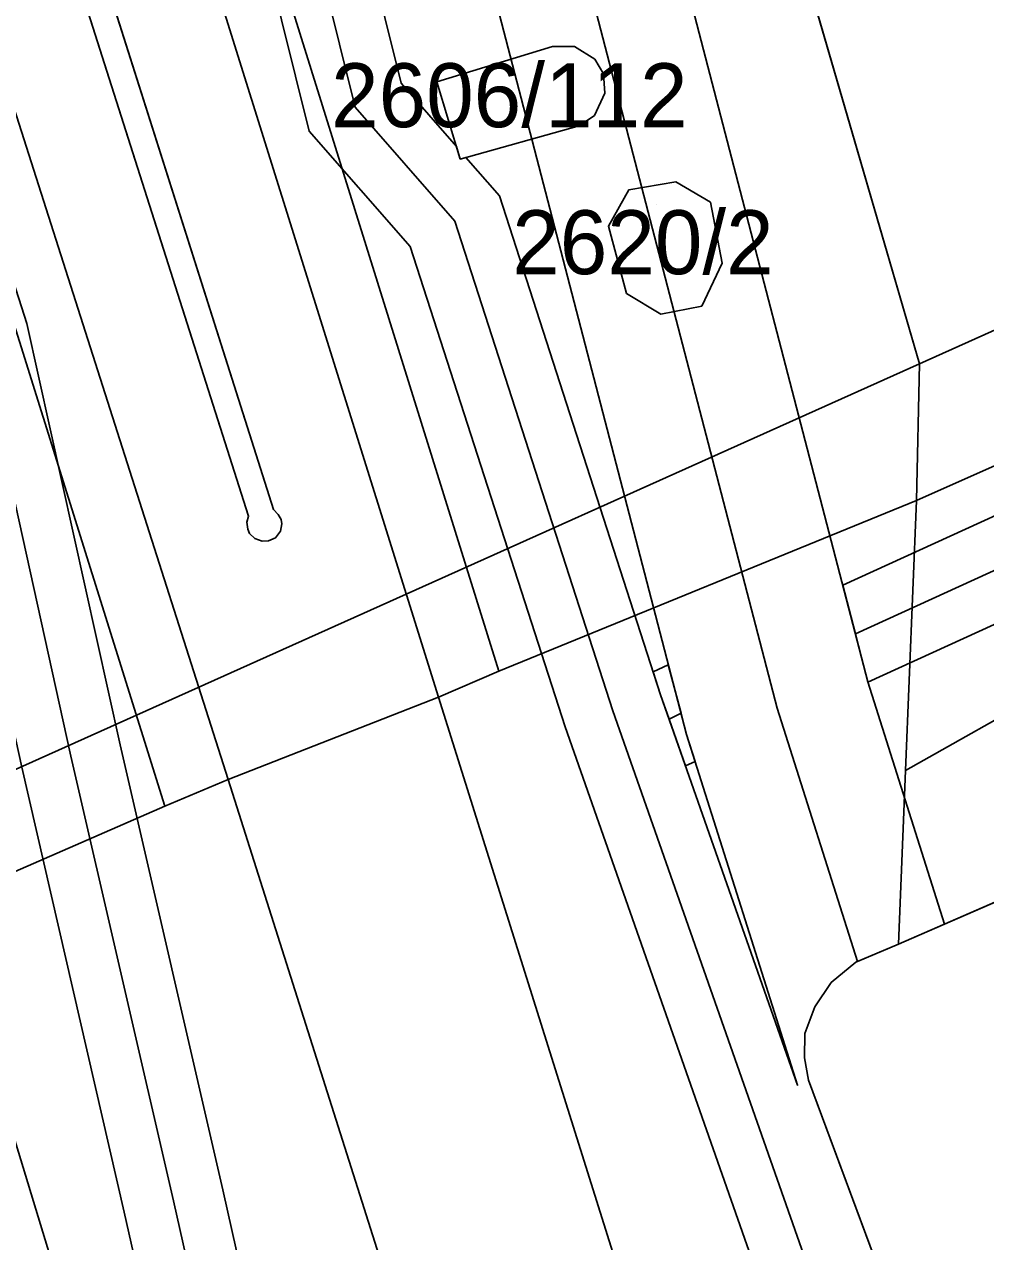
# Model space of a CAD drawing. Extents: x -263423 to -261326, y -1240067 to -1237864.
# Drawn here: x -262699.95 to -262669.87, y -1239884.91 to -1239846.82 of the extents above; entities that cross this region are included whole.
import ezdxf

# ---------------------------------------------------------------- set-up
doc = ezdxf.new("R2010")
doc.units = 0
for name, color, linetype in [('body_kn', 7, 'Continuous'), ('kladpar_druhypozemkov', 7, 'Continuous'), ('kladpar_hranice', 7, 'Continuous'), ('kladpar_parcelnecisla', 7, 'Continuous'), ('kladpar_plochy', 7, 'Continuous'), ('linie', 7, 'Continuous'), ('tarchy_linie', 7, 'Continuous'), ('zappar_hrandruhpozemk', 7, 'Continuous')]:
    doc.layers.add(name, color=color, linetype=linetype)

msp = doc.modelspace()

# ---------------------------------------------------------------- linework, layer by layer
at = {"layer": 'body_kn'}
for p, q in [((-262683.42, -1239847.51), (-262683.42, -1239847.51)), ((-262682.73, -1239847.51), (-262682.73, -1239847.51)), ((-262682.1, -1239847.91), (-262682.1, -1239847.91)), ((-262681.83, -1239848.37), (-262681.83, -1239848.37)), ((-262688.16, -1239848.66), (-262688.16, -1239848.66)), ((-262687.04, -1239848.62), (-262687.04, -1239848.62)), ((-262687.04, -1239848.62), (-262687.04, -1239848.62)), ((-262681.78, -1239848.97), (-262681.78, -1239848.97)), ((-262689.6, -1239849.41), (-262689.6, -1239849.41)), ((-262682.11, -1239849.67), (-262682.11, -1239849.67)), ((-262691.04, -1239850.16), (-262691.04, -1239850.16)), ((-262682.59, -1239850), (-262682.59, -1239850)), ((-262686.43, -1239850.64), (-262686.43, -1239850.64)), ((-262686.31, -1239851.04), (-262686.31, -1239851.04)), ((-262686.13, -1239850.99), (-262686.13, -1239850.99)), ((-262679.56, -1239851.75), (-262679.56, -1239851.75)), ((-262685.08, -1239852.19), (-262685.08, -1239852.19)), ((-262681.03, -1239852), (-262681.03, -1239852)), ((-262678.48, -1239852.39), (-262678.48, -1239852.39)), ((-262678.48, -1239852.39), (-262678.48, -1239852.39)), ((-262686.48, -1239852.98), (-262686.48, -1239852.98)), ((-262681.67, -1239853.14), (-262681.67, -1239853.14)), ((-262687.88, -1239853.77), (-262687.88, -1239853.77)), ((-262678.11, -1239854.3), (-262678.11, -1239854.3)), ((-262681.11, -1239855.24), (-262681.11, -1239855.24)), ((-262678.75, -1239855.64), (-262678.75, -1239855.64)), ((-262680.03, -1239855.89), (-262680.03, -1239855.89)), ((-262699.87, -1239856.18), (-262699.87, -1239856.18)), ((-262671.94, -1239857.45), (-262671.94, -1239857.45)), ((-262672.03, -1239861.72), (-262672.03, -1239861.72)), ((-262672.03, -1239861.72), (-262672.03, -1239861.72)), ((-262692.15, -1239862), (-262692.15, -1239862)), ((-262692.01, -1239862.16), (-262692.01, -1239862.16)), ((-262692.99, -1239862.4), (-262692.99, -1239862.4)), ((-262692.99, -1239862.4), (-262692.99, -1239862.4)), ((-262692.93, -1239862.21), (-262692.93, -1239862.21)), ((-262691.91, -1239862.32), (-262691.91, -1239862.32)), ((-262691.89, -1239862.45), (-262691.89, -1239862.45)), ((-262692.96, -1239862.62), (-262692.96, -1239862.62)), ((-262692.9, -1239862.75), (-262692.9, -1239862.75)), ((-262692.74, -1239862.91), (-262692.74, -1239862.91)), ((-262692.09, -1239862.89), (-262692.09, -1239862.89)), ((-262691.93, -1239862.68), (-262691.93, -1239862.68)), ((-262692.51, -1239862.99), (-262692.51, -1239862.99)), ((-262692.31, -1239862.98), (-262692.31, -1239862.98)), ((-262674.34, -1239864.37), (-262674.34, -1239864.37)), ((-262673.94, -1239865.89), (-262673.94, -1239865.89)), ((-262673.94, -1239865.89), (-262673.94, -1239865.89)), ((-262685.1, -1239867.06), (-262685.1, -1239867.06)), ((-262680.27, -1239867.08), (-262680.27, -1239867.08)), ((-262680.27, -1239867.08), (-262680.27, -1239867.08)), ((-262679.8, -1239866.86), (-262679.8, -1239866.86)), ((-262673.55, -1239867.4), (-262673.55, -1239867.4)), ((-262673.55, -1239867.41), (-262673.55, -1239867.41)), ((-262680.04, -1239867.8), (-262680.04, -1239867.8)), ((-262686.99, -1239867.88), (-262686.99, -1239867.88)), ((-262686.99, -1239867.88), (-262686.99, -1239867.88)), ((-262676.39, -1239868.22), (-262676.39, -1239868.22)), ((-262681.53, -1239868.3), (-262681.53, -1239868.3)), ((-262679.77, -1239868.56), (-262679.77, -1239868.56)), ((-262679.77, -1239868.56), (-262679.77, -1239868.56)), ((-262679.4, -1239868.38), (-262679.4, -1239868.38)), ((-262683.02, -1239868.8), (-262683.02, -1239868.8)), ((-262696.95, -1239869.37), (-262696.95, -1239869.37)), ((-262679.23, -1239869.04), (-262679.23, -1239869.04)), ((-262698.49, -1239869.72), (-262698.49, -1239869.72)), ((-262679.26, -1239870.02), (-262679.26, -1239870.02)), ((-262678.96, -1239869.89), (-262678.96, -1239869.89)), ((-262693.57, -1239870.45), (-262693.57, -1239870.45)), ((-262693.57, -1239870.45), (-262693.57, -1239870.45)), ((-262672.37, -1239870.17), (-262672.37, -1239870.17)), ((-262695.55, -1239871.29), (-262695.55, -1239871.29)), ((-262671.15, -1239874.98), (-262671.15, -1239874.98)), ((-262672.59, -1239875.61), (-262672.59, -1239875.61)), ((-262673.93, -1239876.17), (-262673.93, -1239876.17)), ((-262673.88, -1239876.15), (-262673.88, -1239876.15)), ((-262674.7, -1239876.81), (-262674.7, -1239876.81)), ((-262675.21, -1239877.57), (-262675.21, -1239877.57)), ((-262675.53, -1239878.4), (-262675.53, -1239878.4)), ((-262675.54, -1239879.16), (-262675.54, -1239879.16)), ((-262675.75, -1239880.02), (-262675.75, -1239880.02)), ((-262675.41, -1239879.86), (-262675.41, -1239879.86)), ((-262693.74, -1239883.29), (-262693.74, -1239883.29)), ((-262695.28, -1239883.64), (-262695.28, -1239883.64)), ((-262696.82, -1239883.99), (-262696.82, -1239883.99))]:
    msp.add_line(p, q, dxfattribs=at)
at = {"layer": 'kladpar_druhypozemkov'}
for p, q in [((-262684.11, -1239848.84), (-262684.11, -1239848.84)), ((-262680.16, -1239852.45), (-262680.16, -1239852.45))]:
    msp.add_line(p, q, dxfattribs=at)
at = {"layer": 'kladpar_hranice'}
for points in [[(-262692.99, -1239862.4), (-262692.93, -1239862.21), (-262714.7, -1239793.85)], [(-262714.7, -1239793.85), (-262692.93, -1239862.21)], [(-262713.85, -1239793.61), (-262692.15, -1239862), (-262692.01, -1239862.16), (-262691.91, -1239862.32), (-262691.89, -1239862.45), (-262691.93, -1239862.68), (-262692.09, -1239862.89), (-262692.31, -1239862.98), (-262692.51, -1239862.99), (-262692.74, -1239862.91), (-262692.9, -1239862.75), (-262692.96, -1239862.62), (-262692.99, -1239862.4)], [(-262692.93, -1239862.21), (-262692.99, -1239862.4), (-262692.96, -1239862.62), (-262692.9, -1239862.75), (-262692.74, -1239862.91), (-262692.51, -1239862.99), (-262692.31, -1239862.98), (-262692.09, -1239862.89), (-262691.93, -1239862.68), (-262691.89, -1239862.45), (-262691.91, -1239862.32), (-262692.01, -1239862.16), (-262692.15, -1239862), (-262713.85, -1239793.61)], [(-262686.78, -1239809.35), (-262684.33, -1239817.9), (-262683.63, -1239817.77), (-262683.37, -1239818.54), (-262682.24, -1239822.49), (-262682.63, -1239822.68), (-262680.93, -1239828.11), (-262680.48, -1239828.04), (-262679.23, -1239832.57), (-262679.61, -1239832.76), (-262677.91, -1239838.12), (-262677.6, -1239838.06), (-262676.46, -1239841.89), (-262671.94, -1239857.45), (-262672.03, -1239861.72), (-262672.37, -1239870.17), (-262672.59, -1239875.61), (-262673.93, -1239876.17), (-262674.7, -1239876.81), (-262675.21, -1239877.57), (-262675.53, -1239878.4), (-262675.54, -1239879.16), (-262675.41, -1239879.86), (-262662.51, -1239914.58)], [(-262663.27, -1239837.29), (-262662.12, -1239836.92), (-262662.31, -1239836.21), (-262659.95, -1239835.27), (-262658.67, -1239834.7), (-262657.92, -1239836.87), (-262659.19, -1239837.5), (-262657.24, -1239843.63), (-262654.63, -1239842.43), (-262652.39, -1239841.35), (-262648.06, -1239839.46), (-262648.88, -1239837.55), (-262647.79, -1239836.98), (-262650.38, -1239830.98), (-262640.17, -1239826.56), (-262633.99, -1239840.42), (-262649.81, -1239847.42), (-262651.98, -1239848.49), (-262671.94, -1239857.45), (-262676.46, -1239841.89), (-262663.27, -1239837.29)], [(-262687.04, -1239848.62), (-262683.42, -1239847.51), (-262682.73, -1239847.51), (-262682.1, -1239847.91), (-262681.83, -1239848.37), (-262681.78, -1239848.97), (-262682.11, -1239849.67), (-262682.59, -1239850), (-262686.31, -1239851.04), (-262687.04, -1239848.62)], [(-262683.42, -1239847.51), (-262687.04, -1239848.62), (-262686.31, -1239851.04), (-262682.59, -1239850), (-262682.11, -1239849.67), (-262681.78, -1239848.97), (-262681.83, -1239848.37), (-262682.1, -1239847.91), (-262682.73, -1239847.51), (-262683.42, -1239847.51)], [(-262666.09, -1239872.77), (-262672.59, -1239875.61), (-262672.37, -1239870.17), (-262672.03, -1239861.72), (-262671.94, -1239857.45), (-262651.98, -1239848.49)], [(-262678.48, -1239852.39), (-262678.11, -1239854.3), (-262678.75, -1239855.64), (-262680.03, -1239855.89), (-262681.11, -1239855.24), (-262681.67, -1239853.14), (-262681.03, -1239852), (-262679.56, -1239851.75), (-262678.48, -1239852.39)], [(-262678.11, -1239854.3), (-262678.48, -1239852.39), (-262679.56, -1239851.75), (-262681.03, -1239852), (-262681.67, -1239853.14), (-262681.11, -1239855.24), (-262680.03, -1239855.89), (-262678.75, -1239855.64), (-262678.11, -1239854.3)], [(-262662.51, -1239914.58), (-262675.41, -1239879.86), (-262675.54, -1239879.16), (-262675.53, -1239878.4), (-262675.21, -1239877.57), (-262674.7, -1239876.81), (-262673.93, -1239876.17), (-262672.59, -1239875.61), (-262666.09, -1239872.77)]]:
    msp.add_lwpolyline(points, dxfattribs=at)
at = {"layer": 'kladpar_plochy'}
for p, q in [((-262714.7, -1239793.85), (-262692.93, -1239862.21)), ((-262692.15, -1239862), (-262713.85, -1239793.61)), ((-262676.46, -1239841.89), (-262671.94, -1239857.45)), ((-262683.42, -1239847.51), (-262687.04, -1239848.62)), ((-262682.73, -1239847.51), (-262683.42, -1239847.51)), ((-262682.1, -1239847.91), (-262682.73, -1239847.51)), ((-262681.83, -1239848.37), (-262682.1, -1239847.91)), ((-262681.78, -1239848.97), (-262681.83, -1239848.37)), ((-262687.04, -1239848.62), (-262686.31, -1239851.04)), ((-262682.11, -1239849.67), (-262681.78, -1239848.97)), ((-262682.59, -1239850), (-262682.11, -1239849.67)), ((-262686.31, -1239851.04), (-262682.59, -1239850)), ((-262679.56, -1239851.75), (-262681.03, -1239852)), ((-262678.48, -1239852.39), (-262679.56, -1239851.75)), ((-262681.03, -1239852), (-262681.67, -1239853.14)), ((-262678.11, -1239854.3), (-262678.48, -1239852.39)), ((-262681.67, -1239853.14), (-262681.11, -1239855.24)), ((-262678.75, -1239855.64), (-262678.11, -1239854.3)), ((-262681.11, -1239855.24), (-262680.03, -1239855.89)), ((-262680.03, -1239855.89), (-262678.75, -1239855.64)), ((-262671.94, -1239857.45), (-262672.03, -1239861.72)), ((-262672.03, -1239861.72), (-262672.37, -1239870.17)), ((-262692.01, -1239862.16), (-262692.15, -1239862)), ((-262691.91, -1239862.32), (-262692.01, -1239862.16)), ((-262692.93, -1239862.21), (-262692.99, -1239862.4)), ((-262692.99, -1239862.4), (-262692.96, -1239862.62)), ((-262691.93, -1239862.68), (-262691.89, -1239862.45)), ((-262691.89, -1239862.45), (-262691.91, -1239862.32)), ((-262692.96, -1239862.62), (-262692.9, -1239862.75)), ((-262692.9, -1239862.75), (-262692.74, -1239862.91)), ((-262692.74, -1239862.91), (-262692.51, -1239862.99)), ((-262692.31, -1239862.98), (-262692.09, -1239862.89)), ((-262692.09, -1239862.89), (-262691.93, -1239862.68)), ((-262692.51, -1239862.99), (-262692.31, -1239862.98)), ((-262672.37, -1239870.17), (-262672.59, -1239875.61)), ((-262672.59, -1239875.61), (-262666.09, -1239872.77)), ((-262673.93, -1239876.17), (-262672.59, -1239875.61)), ((-262672.59, -1239875.61), (-262673.93, -1239876.17)), ((-262674.7, -1239876.81), (-262673.93, -1239876.17)), ((-262673.93, -1239876.17), (-262674.7, -1239876.81)), ((-262675.21, -1239877.57), (-262674.7, -1239876.81)), ((-262674.7, -1239876.81), (-262675.21, -1239877.57)), ((-262675.53, -1239878.4), (-262675.21, -1239877.57)), ((-262675.21, -1239877.57), (-262675.53, -1239878.4)), ((-262675.54, -1239879.16), (-262675.53, -1239878.4)), ((-262675.53, -1239878.4), (-262675.54, -1239879.16)), ((-262675.41, -1239879.86), (-262675.54, -1239879.16)), ((-262675.54, -1239879.16), (-262675.41, -1239879.86)), ((-262662.51, -1239914.58), (-262675.41, -1239879.86)), ((-262675.41, -1239879.86), (-262662.51, -1239914.58))]:
    msp.add_line(p, q, dxfattribs=at)
for points in [[(-262713.85, -1239793.61), (-262692.15, -1239862), (-262692.01, -1239862.16), (-262691.91, -1239862.32), (-262691.89, -1239862.45), (-262691.93, -1239862.68), (-262692.09, -1239862.89), (-262692.31, -1239862.98), (-262692.51, -1239862.99), (-262692.74, -1239862.91), (-262692.9, -1239862.75), (-262692.96, -1239862.62), (-262692.99, -1239862.4), (-262692.93, -1239862.21), (-262714.7, -1239793.85)], [(-262666.09, -1239872.77), (-262672.59, -1239875.61), (-262672.37, -1239870.17), (-262672.03, -1239861.72), (-262671.94, -1239857.45), (-262651.98, -1239848.49)]]:
    msp.add_lwpolyline(points, dxfattribs=at)
for points in [[(-262663.27, -1239837.29), (-262662.12, -1239836.92), (-262662.31, -1239836.21), (-262659.95, -1239835.27), (-262658.67, -1239834.7), (-262657.92, -1239836.87), (-262659.19, -1239837.5), (-262657.24, -1239843.63), (-262654.63, -1239842.43), (-262652.39, -1239841.35), (-262648.06, -1239839.46), (-262648.88, -1239837.55), (-262647.79, -1239836.98), (-262650.38, -1239830.98), (-262640.17, -1239826.56), (-262633.99, -1239840.42), (-262649.81, -1239847.42), (-262651.98, -1239848.49), (-262671.94, -1239857.45), (-262676.46, -1239841.89)], [(-262687.04, -1239848.62), (-262683.42, -1239847.51), (-262682.73, -1239847.51), (-262682.1, -1239847.91), (-262681.83, -1239848.37), (-262681.78, -1239848.97), (-262682.11, -1239849.67), (-262682.59, -1239850), (-262686.31, -1239851.04)], [(-262678.48, -1239852.39), (-262678.11, -1239854.3), (-262678.75, -1239855.64), (-262680.03, -1239855.89), (-262681.11, -1239855.24), (-262681.67, -1239853.14), (-262681.03, -1239852), (-262679.56, -1239851.75)]]:
    msp.add_lwpolyline(points, close=True, dxfattribs=at)
at = {"layer": 'linie'}
msp.add_lwpolyline([(-262521.46, -1239790.07), (-262540.33, -1239798.65), (-262560.41, -1239807.74), (-262562.89, -1239808.81), (-262563.41, -1239809.03), (-262572.52, -1239812.91), (-262575.06, -1239814.02), (-262575.26, -1239814.11), (-262577.3, -1239815.05), (-262595.03, -1239823), (-262607.52, -1239828.24), (-262633.99, -1239840.42), (-262649.81, -1239847.42), (-262651.98, -1239848.49), (-262671.94, -1239857.45), (-262714.44, -1239876.51), (-262740.08, -1239884.8)], dxfattribs=at)
at = {"layer": 'tarchy_linie'}
msp.add_line((-262679.77, -1239868.56), (-262679.4, -1239868.38), dxfattribs=at)
for points in [[(-262876.1, -1239267.26), (-262859.65, -1239272.11), (-262836.46, -1239332.83), (-262813.8, -1239395.79), (-262782.96, -1239480.21), (-262751.68, -1239564.86), (-262738.56, -1239596.25), (-262720.83, -1239681.08), (-262703.16, -1239765.24), (-262676.39, -1239868.22), (-262673.88, -1239876.15)], [(-262673.94, -1239865.89), (-262591.1, -1239828.06), (-262563.05, -1239815.33), (-262497.85, -1239786.86), (-262417.23, -1239749.97)], [(-262700.29, -1239764.57), (-262673.55, -1239867.4), (-262671.15, -1239874.98), (-262672.59, -1239875.61), (-262673.88, -1239876.15), (-262673.93, -1239876.17), (-262674.7, -1239876.81), (-262675.21, -1239877.57), (-262675.53, -1239878.4), (-262675.54, -1239879.16), (-262675.41, -1239879.86), (-262662.51, -1239914.58), (-262657.08, -1239929.21), (-262650.11, -1239948.02), (-262649.29, -1239949.42), (-262648.47, -1239950.57), (-262647.52, -1239951.53), (-262646.71, -1239952.19), (-262642.79, -1239964.57), (-262676.62, -1239978.96), (-262706.54, -1239880.67), (-262742.27, -1239779.37)], [(-262704.88, -1239770.36), (-262679.23, -1239869.04), (-262675.75, -1239880.02), (-262680.04, -1239867.8), (-262685.08, -1239852.19), (-262686.13, -1239850.99), (-262686.31, -1239851.04), (-262686.43, -1239850.64), (-262688.16, -1239848.66), (-262695.33, -1239819.8), (-262695.68, -1239819.16), (-262695.52, -1239819.07), (-262696.63, -1239814.58), (-262697.18, -1239812.62), (-262697.12, -1239812.6), (-262698.35, -1239807.65), (-262704.2, -1239785.83), (-262704.62, -1239773.91), (-262704.88, -1239770.36)], [(-262733.86, -1239786.06), (-262731.31, -1239790.5), (-262727.77, -1239796.86), (-262723.05, -1239806.16), (-262717.47, -1239818.88), (-262715.31, -1239824.82), (-262709.31, -1239838.88), (-262708.04, -1239840.99), (-262702.91, -1239857), (-262700.03, -1239870.07), (-262696.82, -1239883.99), (-262694.57, -1239893.97), (-262689.49, -1239914.36), (-262686.73, -1239925.28), (-262678.36, -1239950.89), (-262673.78, -1239965.52), (-262673.54, -1239968), (-262672.3, -1239970.93), (-262673.02, -1239971.24), (-262701.12, -1239878.89), (-262733.86, -1239786.06)], [(-262497.22, -1239788.28), (-262562.42, -1239816.75), (-262590.46, -1239829.47), (-262673.55, -1239867.41), (-262673.55, -1239867.4), (-262673.94, -1239865.89), (-262674.34, -1239864.37), (-262591.74, -1239826.65), (-262565.09, -1239814.55)], [(-262701.41, -1239808.43), (-262691.04, -1239850.16), (-262687.88, -1239853.77), (-262683.02, -1239868.8), (-262675.02, -1239891.62), (-262660.7, -1239928.6), (-262653.54, -1239953.87), (-262651.61, -1239958.73), (-262670.45, -1239967.28), (-262670.68, -1239964.9), (-262675.36, -1239949.93), (-262683.71, -1239924.4), (-262686.43, -1239913.6), (-262691.51, -1239893.25), (-262693.74, -1239883.29), (-262696.95, -1239869.37), (-262699.87, -1239856.18), (-262705.16, -1239839.69), (-262706.49, -1239837.44), (-262712.37, -1239823.66), (-262714.55, -1239817.7), (-262720.21, -1239804.82)], [(-262699.88, -1239808.04), (-262689.6, -1239849.41), (-262686.48, -1239852.98), (-262681.53, -1239868.3), (-262673.54, -1239891.07), (-262659.2, -1239928.1), (-262652.05, -1239953.36), (-262649.56, -1239959.61), (-262671.22, -1239969.44), (-262672, -1239967.61), (-262672.23, -1239965.21), (-262676.86, -1239950.41), (-262685.22, -1239924.84), (-262687.96, -1239913.98), (-262693.04, -1239893.61), (-262695.28, -1239883.64), (-262698.49, -1239869.72), (-262701.39, -1239856.59), (-262706.6, -1239840.34), (-262707.9, -1239838.16), (-262713.84, -1239824.24), (-262716.01, -1239818.29), (-262721.63, -1239805.49)], [(-262680.27, -1239867.08), (-262679.8, -1239866.86), (-262679.4, -1239868.38), (-262679.23, -1239869.04), (-262678.96, -1239869.89), (-262679.26, -1239870.02), (-262679.77, -1239868.56), (-262680.04, -1239867.8), (-262680.27, -1239867.08)]]:
    msp.add_lwpolyline(points, dxfattribs=at)
at = {"layer": 'zappar_hrandruhpozemk'}
for p, q in [((-262705.2, -1239802.58), (-262685.1, -1239867.06)), ((-262707.2, -1239803.21), (-262686.99, -1239867.88)), ((-262713.63, -1239807.6), (-262693.57, -1239870.45)), ((-262693.57, -1239870.45), (-262686.99, -1239867.88)), ((-262686.99, -1239867.88), (-262665.81, -1239935.33)), ((-262672.47, -1239936.95), (-262693.57, -1239870.45)), ((-262713.68, -1239879.19), (-262695.55, -1239871.29))]:
    msp.add_line(p, q, dxfattribs=at)
for points in [[(-262715.29, -1239808.21), (-262695.55, -1239871.29), (-262693.57, -1239870.45)], [(-262672.03, -1239861.72), (-262573.53, -1239817.9), (-262572.34, -1239817.05)], [(-262672.03, -1239861.72), (-262685.1, -1239867.06), (-262686.99, -1239867.88)], [(-262660.83, -1239864.32), (-262667.86, -1239867.63), (-262672.37, -1239870.17)]]:
    msp.add_lwpolyline(points, dxfattribs=at)

# ---------------------------------------------------------------- texts
at = {"layer": 'kladpar_parcelnecisla'}
for s, p in [('2606/112', (-262690.348, -1239850.04)), ('2620/2', (-262684.681, -1239854.64))]:
    msp.add_text(s, height=2, dxfattribs=at).set_placement(p)

doc.saveas('drawing.dxf')
